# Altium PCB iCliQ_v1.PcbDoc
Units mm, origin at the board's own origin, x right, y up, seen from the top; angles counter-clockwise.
Board outline 70.5 x 34 mm, 4 copper layers (L1 (Signal), L2 (GND), L3 (GND), L4 (Signal)), stack 1.57 mm thick; 50 components, 34 nets, 172 pads, 106 vias.
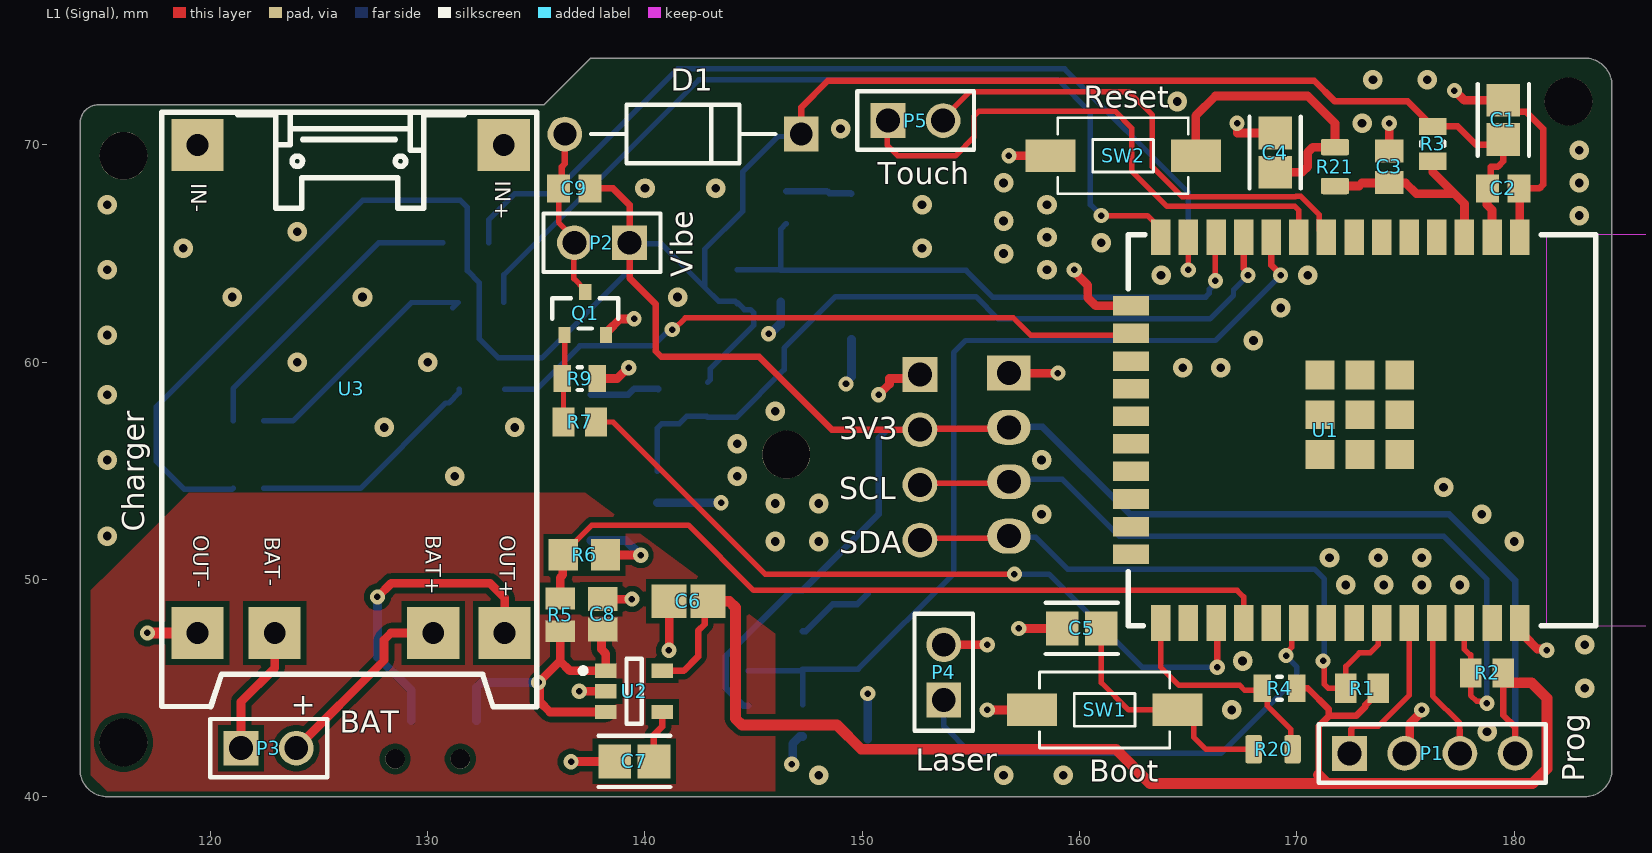
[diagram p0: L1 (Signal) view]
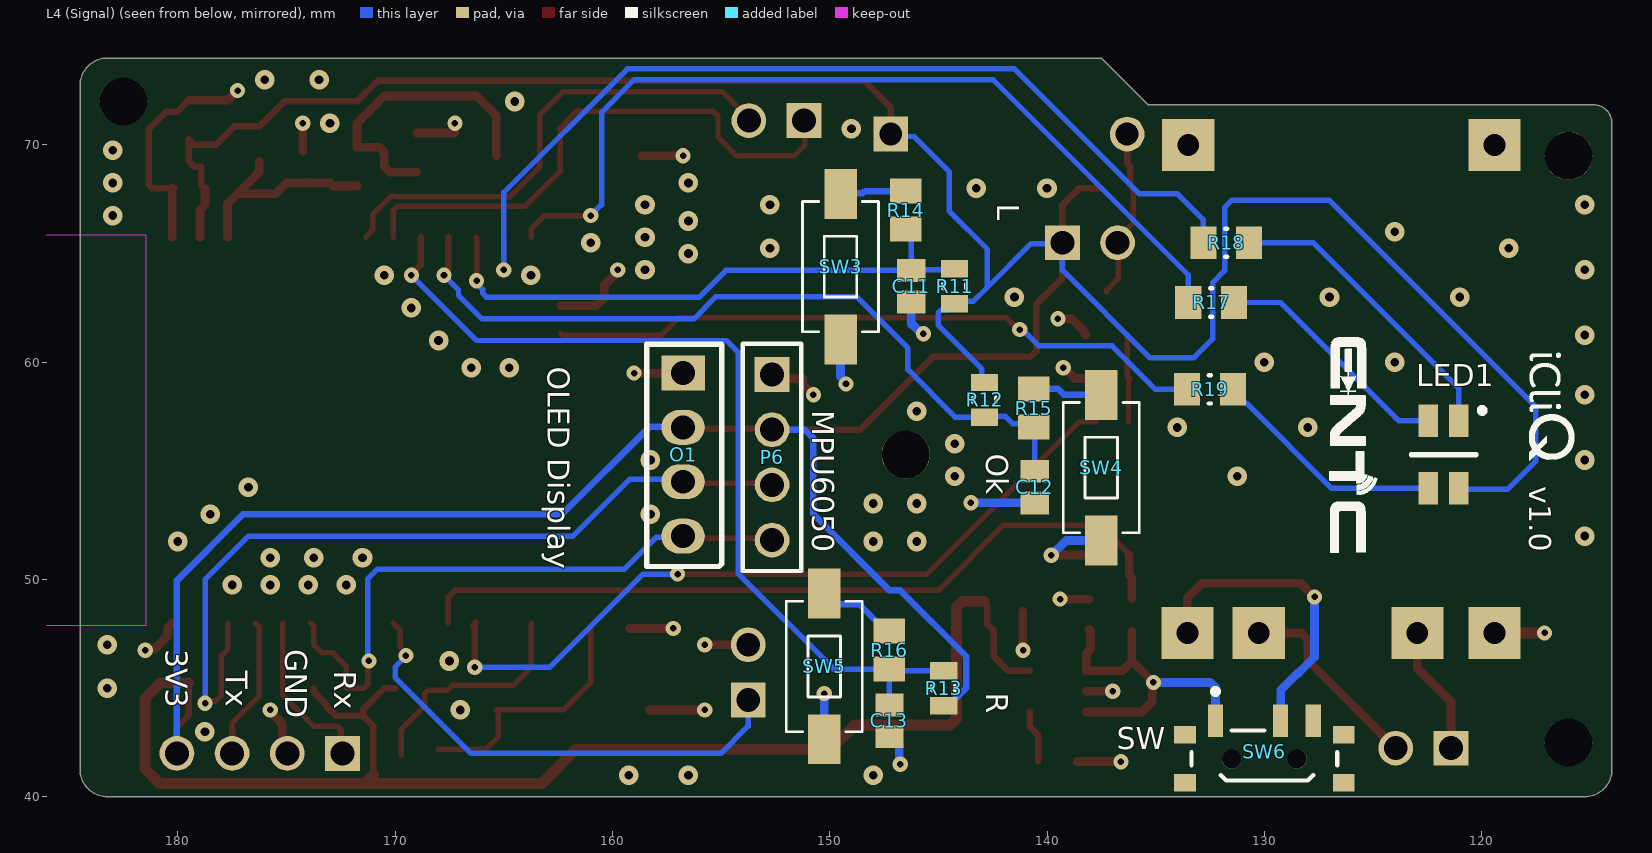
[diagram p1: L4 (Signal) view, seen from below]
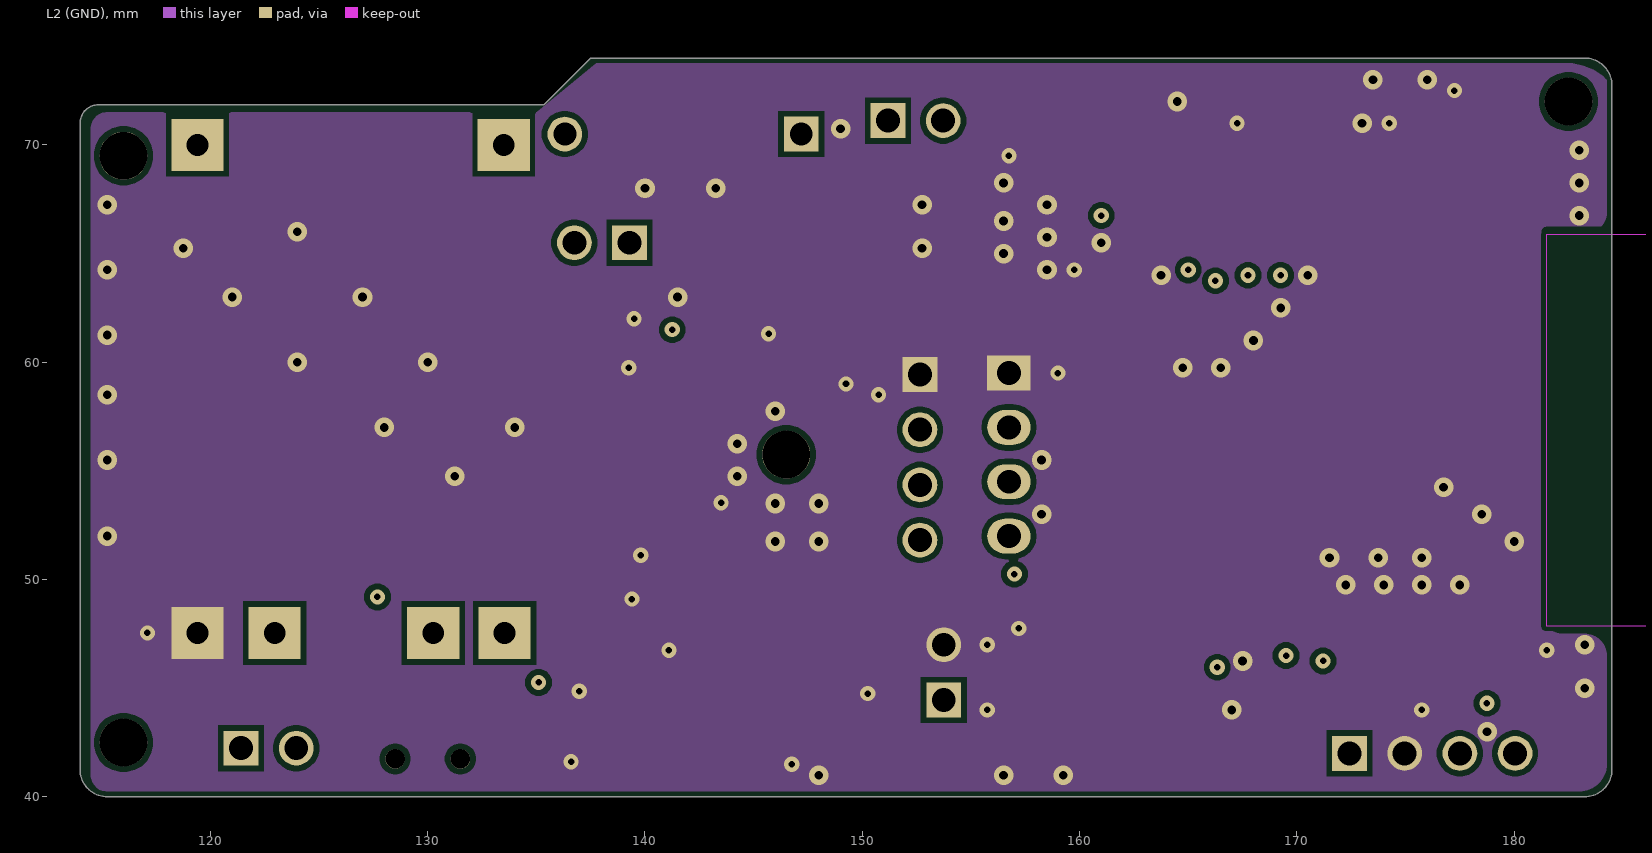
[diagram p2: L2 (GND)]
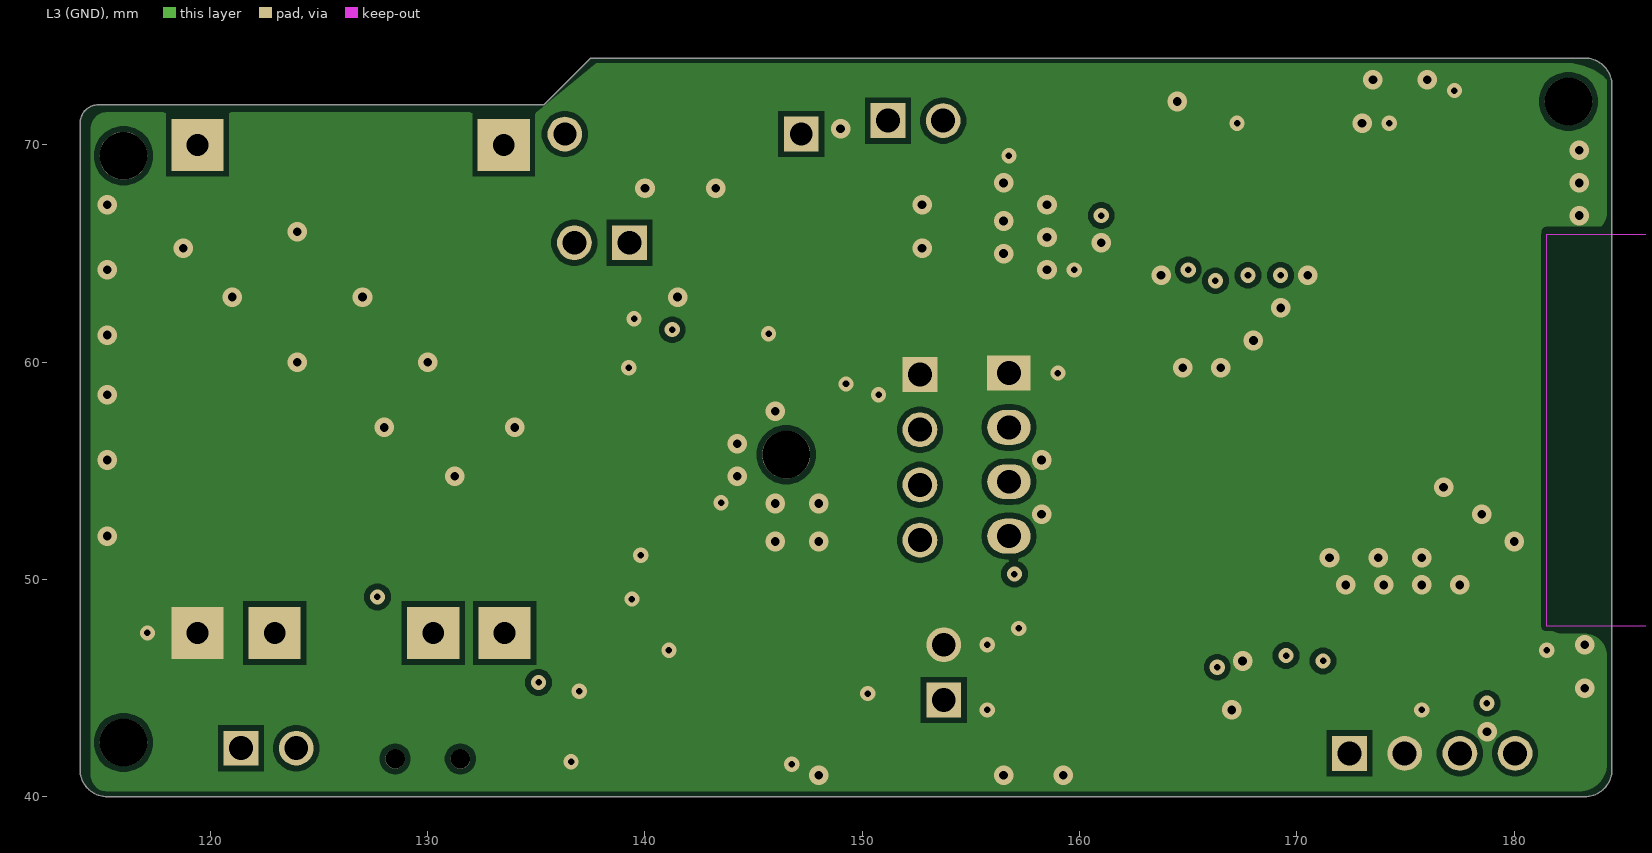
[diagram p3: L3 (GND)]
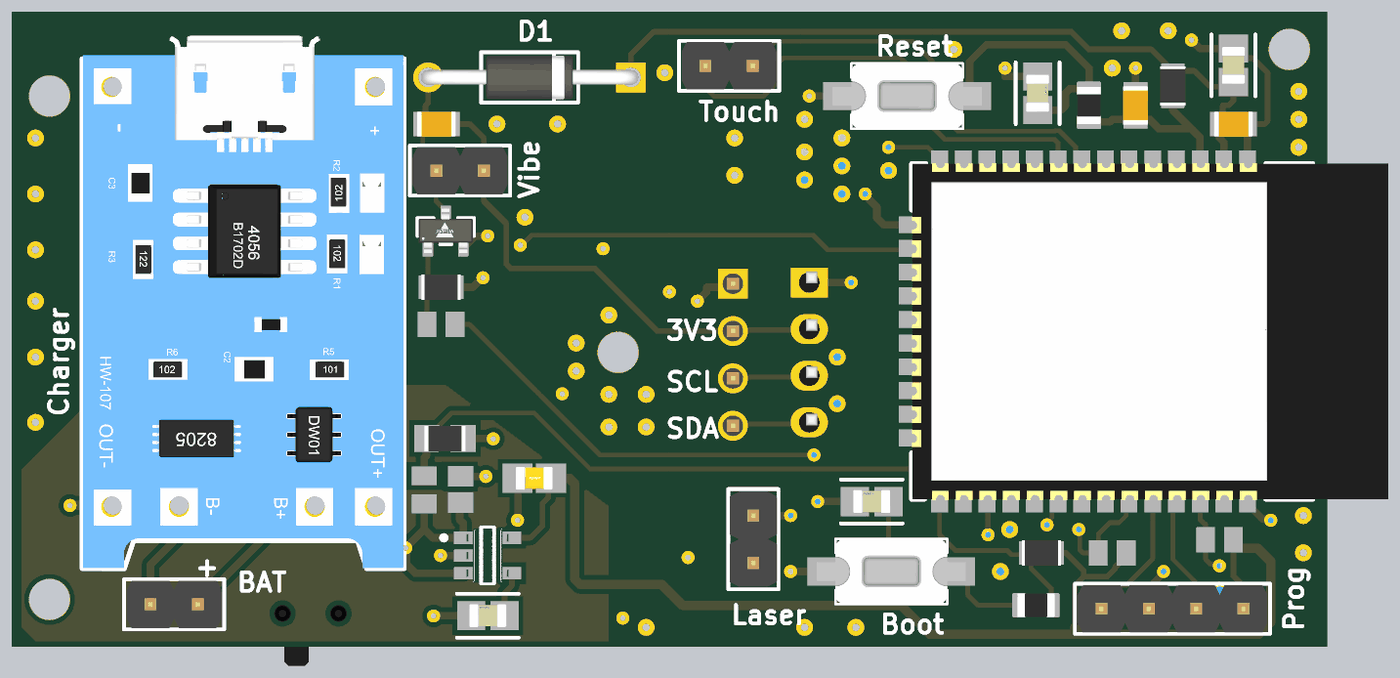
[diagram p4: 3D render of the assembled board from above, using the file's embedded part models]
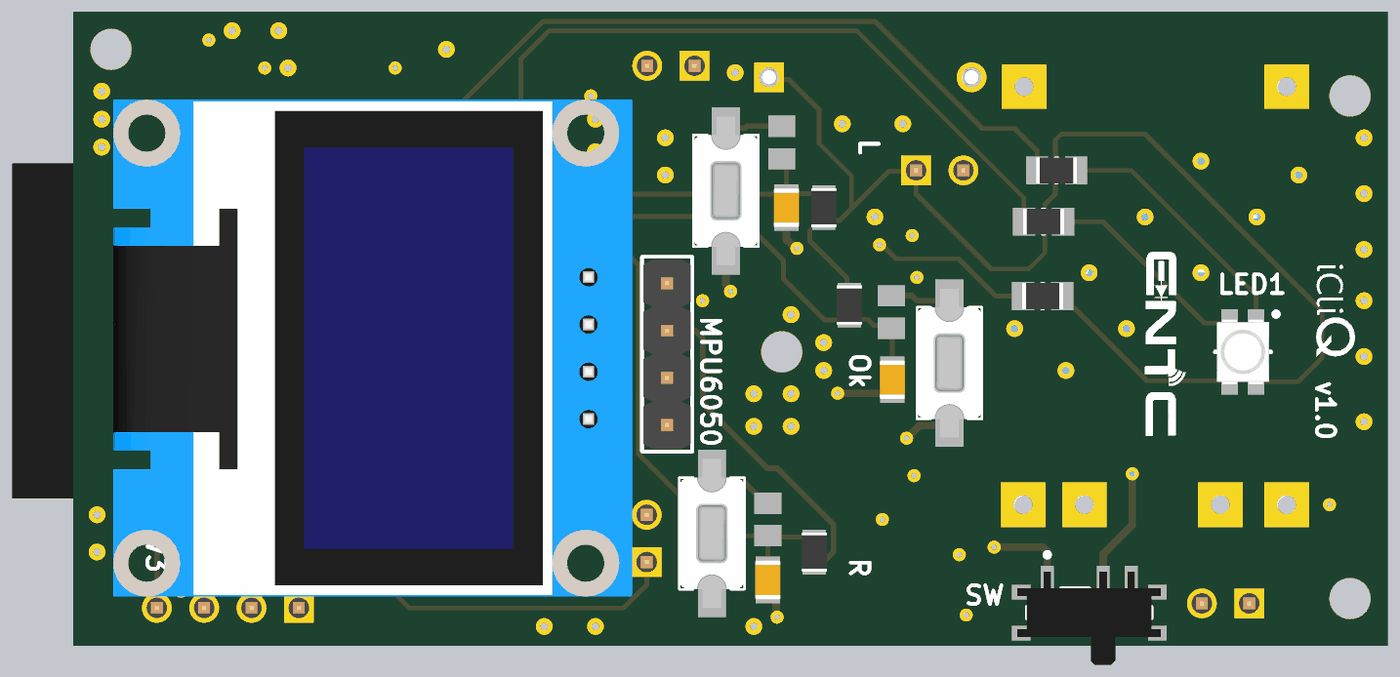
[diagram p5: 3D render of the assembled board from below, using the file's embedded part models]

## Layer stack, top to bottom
Top Solder: solder mask 0.0254, SM-001, Dk 4
L1 (Signal): signal copper 0.035
Dielectric 1: prepreg 0.2, PP-017, Dk 4.6
L2 (GND): signal copper 0.0175
Dielectric 3: core 1.065, Core-039, Dk 4.6
L3 (GND): signal copper 0.0175
Dielectric 5: prepreg 0.2, PP-017, Dk 4.6
L4 (Signal): signal copper 0.035
Bottom Solder: solder mask 0.0254, SM-001, Dk 4

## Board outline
114,41.27 114,71 cw(c114.842,71) 114.842,71.842 135.342,71.842 137.5,74 183.23,74 cw(c183.23,72.73) 184.5,72.73 184.5,41.27 cw(c183.23,41.27) 183.23,40 115.27,40 cw(c115.27,41.27)

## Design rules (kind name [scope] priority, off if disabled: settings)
Clearance [All] p1: gap=0.254 ignorepadtopadclearanceinfootprint=TRUE except(0.127: SMDPad-SMDPad; 0.2: Arc-Arc Arc-Track Arc-Text Track-Track Track-Text SMDPad-Text THPad-Text Via-Text Fill-Text Poly-Text Region-Text Text-Text Text-Hole; 0.33: Arc-THPad Track-THPad)
MinimumSolderMaskSliver [All] p1: minsoldermaskwidth=0.1
PolygonConnect [All] p1: connectstyle=Direct reliefconductorwidth=0.254 reliefentries=4 polygonreliefangle="90 Angle" airgapwidth=0.254
RoutingVias [All] p1: holewidth=0.3 width=0.7 viastyle="Through Hole" minholewidth=0.25 minwidth=0.55 maxholewidth=0.4 maxwidth=0.9
SilkToSilkClearance [All] p1: silktosilkclearance=0.15
SilkToSolderMaskClearance [IsPad] p1: minsilkscreentomaskgap=0.15 clearancetoexposedcopper=TRUE
SolderMaskExpansion [HasFootprint('No Footprint') And OnLayer('L1 (Signal)')] p1: expansion=0.038 istentingtop=FALSE
UnRoutedNet [All] p1: checkbadconnections=TRUE
Width [All] p1: maxlimit=1 minlimit=0.2 preferedwidth=0.3 midlayer1_minwidth=0.254 midlayer1_maxwidth=0.254 midlayer1_prefwidth=0.254 midlayer2_minwidth=0.254 midlayer2_maxwidth=0.254 midlayer2_prefwidth=0.254 minimp=50.000000 maximp=50.000000 favimp=50.000000
26 further rules are at their usual default settings.

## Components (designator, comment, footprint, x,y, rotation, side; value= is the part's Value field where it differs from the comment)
C1 "10uF 10V 0805" FP-C0805C-DG-IPC_A 179.5,71.151 r90 top value=10µF
C2 "Capacitor 100 nF +/-10% 50 V 0805" CAPC2013X95X50LL10T25 179.5,68 r0 top value=100nF
C3 "Capacitor 100 nF +/-10% 50 V 0805" CAPC2013X95X50LL10T25 174.25,69 r270 top value=100nF
C4 "1 nF 50V 0805" FP-C0805C-DN-IPC_A 169,69.651 r270 top value=1nF
C5 "1 nF 50V 0805" FP-C0805C-DN-IPC_A 160.099,47.75 r0 top value=1nF
C6 "2.2 uF 0805" FP-C0805C225K4RACAUTO-IPC_A 142,49 r0 top value=2.2µF
C7 "470 pF 0805" FP-C0805C-DN-IPC_A 139.51,41.631 r0 top value=470pF
C8 "1uF 10V 0805" CAPC2013X140X50LL20T25 138.049,48.398 r270 top value=1µF
C9 "Capacitor 100 nF +/-10% 50 V 0805" CAPC2013X95X50LL10T25 136.75,68 r0 top value=100nF
C11 "Capacitor 100 nF +/-10% 50 V 0805" CAPC2013X95X50LL10T25 146.25,63.5 r90 bottom value=100nF
C12 "Capacitor 100 nF +/-10% 50 V 0805" CAPC2013X95X50LL10T25 140.564,54.254 r90 bottom value=100nF
C13 "Capacitor 100 nF +/-10% 50 V 0805" CAPC2013X95X50LL10T25 147.25,43.5 r90 bottom value=100nF
D1 "1N4001-E3/54" FP-1N4001-E3-54-MFG 141.75,70.5 r180 top
LED1 "RGB LED SMD" 3528_A 121.75,55.75 r270 bottom
O1 "OLED_64" OLED_SSD1306_64 156.75,59.5 r180 bottom locked
P1 "4 pin Header" 61300411121 176.23,42 r0 top
P2 "2 pin header" 61300211121 138.02,65.5 r180 top
P3 "BAT_pins" 61300211121 122.682,42.24 r0 top
P4 "2 pin header" 61300211121 153.75,45.73 r90 top
P5 "Touch Pins" 61300211121 152.451,71.12 r0 top
P6 "MPU6050" 61300411121 152.654,55.626 r270 bottom
Q1 "SI2302 MOSFET" FP-S-03946-MFG 137.25,62.25 r90 top
R1 "2.2K 0805" RESC2013X60X40LL20T25 173,45 r0 top value=2.2k
R2 "2.2K 0805" RESC2013X60X40LL20T25 178.75,45.7 r0 top value=2.2k
R3 "10K 0805" RESC2013X60X35LL10T20 176.25,70.05 r90 top value=10k
R4 "10K 0805" RESC2013X60X35LL10T20 169.2,45 r0 top value=10k
R5 "27K 0805" RESC2013X60X40LL20T25 136.093,48.375 r270 top value=27k
R6 "Resistor 100k +/-1% 0805 125 mW" RESC2013X70X40ML20T20 137.211,51.13 r180 top value=100k
R7 "100 Ohm 0805" RESC2013X60X40LL20T25 137,57.25 r180 top value=100
R9 "10K 0805" RESC2013X60X35LL10T20 137,59.25 r180 top value=10k
R11 "10K 0805" RESC2013X60X35LL10T20 144.25,63.5 r270 bottom value=10k
R12 "10K 0805" RESC2013X60X35LL10T20 142.875,58.268 r90 bottom value=10k
R13 "10K 0805" RESC2013X60X35LL10T20 144.75,45 r270 bottom value=10k
R14 "Resistor 1K +/-5% 0805 500 mW." RESC2013X70X40NL20T20 146.5,67 r270 bottom value=1k
R15 "Resistor 1K +/-5% 0805 500 mW." RESC2013X70X40NL20T20 140.614,57.887 r270 bottom value=1k
R16 "Resistor 1K +/-5% 0805 500 mW." RESC2013X70X40NL20T20 147.25,46.75 r270 bottom value=1k
R17 "Resistor 0R +/- 1% 0805 125 mW" RESC2013X50X35ML15T15 132.45,62.75 r0 bottom value="120 Ohm"
R18 "Resistor 0R +/- 1% 0805 125 mW" RESC2013X50X35ML15T15 131.75,65.5 r0 bottom value="180 Ohm"
R19 "Resistor 0R +/- 1% 0805 125 mW" RESC2013X50X35ML15T15 132.5,58.75 r0 bottom value="120 Ohm"
R20 "Resistor 470R +/-5% 0805 125 mW" RESC0805(2012)_L 168.91,42.189 r0 top value=470
R21 "Resistor 470R +/-5% 0805 125 mW" RESC0805(2012)_L 171.75,69 r270 top value=470
SW1 "nav button" 434121050816 161.15,44 r0 top
SW2 "nav button" 434121050816 162,69.5 r0 top
SW3 "nav button" 434121050816 149.5,64.4 r90 bottom
SW4 "nav button" 434121050816 137.5,55.15 r90 bottom
SW5 "nav button" 434121050816 150.25,46 r90 bottom
SW6 "Switch_ALPS_SSSS811101_eec" ALPS_SSSS811101_0 130,41 r180 bottom
U1 "ESP32-WROOM-32D" ESP32-WROOM-32D 175.025,56.888 r270 top
U2 "3.3v LDO" FP-SOT23-5LD-PL-1-MFG 139.497,44.856 r0 top
U3 "TP4056_6PINS" TP4056_6PINs 126.388,58.062 r0 top locked

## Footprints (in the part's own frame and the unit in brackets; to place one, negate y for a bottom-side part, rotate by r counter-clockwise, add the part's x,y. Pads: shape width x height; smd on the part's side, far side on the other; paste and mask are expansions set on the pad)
3528_A [mm] "Chip LED, 4-Leads, Body 2.8x3.5mm (max), Pitch 1.42mm, IPC Medium Density"
  rect 1.5x0.9 smd: 1(1.55,0.707) 2(1.55,-0.71) 3(-1.55,0.707) 4(-1.55,-0.707)
  silkscreen extent -2.15,-1.5 0.03,1.9, body extent -1.75,-1.4 1.75,1.4, height 1.87
61300211121 [mm] "Pin Header, pitch 2.54 mm, THT, Vertical, single row, 2p"
  rect 1.6x1.6 hole 1.1: 1(-1.27,0)
  round 1.6 hole 1.1: 2(1.27,0)
  silkscreen extent -2.69,-1.35 2.69,1.35, body extent -2.54,-1.27 2.54,1.27, height 8.57
61300411121 [mm] "Pin Header, pitch 2.54 mm, THT, Vertical, single row, 4p"
  rect 1.6x1.6 hole 1.1: 1(-3.81,0)
  round 1.6 hole 1.1: 2(-1.27,0) 3(1.27,0) 4(3.81,0)
  silkscreen extent -5.23,-1.35 5.23,1.35, body extent -5.08,-1.27 5.08,1.27, height 8.57
434121050816 [mm] "6.0*3.5mm vertical type, SMD, height 5.0mm, black actuator, 160gf, T&R"
  rect 2.3x1.5 smd: 1(-3.35,0) 2(3.35,0)
  silkscreen extent -3,-1.75 3,1.75, body extent -4,-1.75 4,1.75, height 5
ALPS_SSSS811101_0 [mm]
  rect 0.7x1.5 smd paste+0 mask+0: 1(-2.25,2.5) 2(0.75,2.5) 3(2.25,2.5)
  rect 1x0.8 smd paste+0 mask+0: 4(-3.65,-0.35) 4(-3.65,1.85) 4(3.65,-0.35) 4(3.65,1.85)
  round 0.9 hole 0.9 unplated paste-1000 mask+0: ""(-1.5,0.75) ""(1.5,0.75)
  silkscreen extent -3.35,-0.25 3.35,3.97, body extent -3.85,-2.05 3.85,2.95, height 1.41
CAPC2013X95X50LL10T25 [mm] "Chip Capacitor, 2-Leads, Body 2.10x1.35mm, IPC High Density"
  rect 1.05x1.3 smd: 1(-0.725,0) 2(0.725,0)
  body extent -1.05,-0.67 1.05,0.67, height 0.95
CAPC2013X140X50LL20T25 [mm] "Chip Capacitor, 2-Leads, Body 2.00x1.25mm, IPC High Density"
  rect 1.1x1.35 smd: 1(-0.7,0) 2(0.7,0)
  body extent -1.1,-0.72 1.1,0.72, height 1.4
ESP32-WROOM-32D [mm] "Chip SMD 39 Pads 18x25.5mm w/ Antenna."
  rect 1.65x0.9 smd: 1(-8.862,5.224) 2(-8.862,3.954) 3(-8.862,2.684) 4(-8.862,1.414) 5(-8.862,0.144) 6(-8.862,-1.126) 7(-8.862,-2.396) 8(-8.862,-3.666) 9(-8.862,-4.936) 10(-8.862,-6.206) 11(-8.862,-7.476) 12(-8.862,-8.746) 13(-8.862,-10.016) 14(-8.862,-11.286) 25(8.888,-11.286) 26(8.888,-10.016) 27(8.888,-8.746) 28(8.888,-7.476) 29(8.888,-6.206) 30(8.888,-4.936) 31(8.888,-3.666) 32(8.888,-2.396) 33(8.888,-1.126) 34(8.888,0.144) 35(8.888,1.414) 36(8.888,2.684) 37(8.888,3.954) 38(8.888,5.224)
  rect 0.9x1.65 smd: 15(-5.707,-12.661) 16(-4.437,-12.661) 17(-3.167,-12.661) 18(-1.897,-12.661) 19(-0.627,-12.661) 20(0.643,-12.661) 21(1.913,-12.661) 22(3.183,-12.661) 23(4.453,-12.661) 24(5.723,-12.661)
  rect 1.33x1.33 smd: 39(-2.531,-0.292) 39(-2.531,-2.127) 39(-2.531,-3.962) 39(-0.696,-3.962) 39(-0.696,-0.292) 39(-0.696,-2.127) 39(1.139,-0.292) 39(1.139,-2.127) 39(1.139,-3.962)
  Keep-Out Layer region: -8.987,6.45 9.013,6.45 9.013,12.75 -8.987,12.75
  silkscreen extent -8.99,-12.79 9.01,8.72, body extent -9.02,-12.77 9.05,12.77, height 3
FP-1N4001-E3-54-MFG [mm]
  rect 1.6x1.6 hole 1.05 paste-1000 mask+0: 1(-5.438,0)
  round 1.6 hole 1.05 paste-1000 mask+0: 2(5.438,0)
  silkscreen extent -4.24,-1.35 4.24,1.35, body extent -5.83,-1.17 5.83,1.17, height 2.35
FP-C0805C225K4RACAUTO-IPC_A [mm]
  rect 1.603x1.556 smd paste+0 mask+0: 1(-0.9,0) 2(0.9,0)
  body extent -2.2,-1.28 2.2,1.28, height 0.25
FP-C0805C-DG-IPC_A [mm]
  rect 1.505x1.556 smd paste+0 mask+0: 1(-0.901,0) 2(0.901,0)
  silkscreen extent -1.65,-1.18 1.65,1.18, body extent -2.15,-1.28 2.15,1.28, height 0.25
FP-C0805C-DN-IPC_A [mm]
  rect 1.505x1.556 smd paste+0 mask+0: 1(-0.901,0) 2(0.901,0)
  silkscreen extent -1.65,-1.18 1.65,1.18, body extent -2.15,-1.28 2.15,1.28, height 0.25
FP-S-03946-MFG [mil]
  rect 29x22 smd paste+0 mask+0: 1(-39,37.5) 2(-39,-37.5) 3(39,0)
  silkscreen extent -28,-60 28,60, body extent -57,-64 57,64, height 10
FP-SOT23-5LD-PL-1-MFG [mm]
  rect 1x0.66 smd paste+0 mask+0: 1(-1.3,0.95) 2(-1.3,0) 3(-1.3,-0.95) 4(1.3,-0.95) 5(1.3,0.95)
  silkscreen extent -2.47,-1.5 0.35,1.5, body extent -1.4,-1.45 1.4,1.45, height 1.45
OLED_SSD1306_64 [mm]
  rect 2x1.6 hole 1.1: 1(0,0)
  oval 2x1.6 hole 1.1: 2(0,-2.5) 3(0,-5) 4(0,-7.5)
  silkscreen extent -1.68,-8.9 1.78,1.33, body extent -25.63,-16.9 2.23,9.8, height 8.47
RESC0805(2012)_L [mm] "Chip Resistor, Body 2.0x1.3mm, IPC High Density"
  rrect25% 0.76x1.3 smd: 1(-0.9,0) 2(0.89,0)
  body extent -1,-0.62 1,0.63, height 0.6
RESC2013X50X35ML15T15 [mm] "Chip Resistor, 2-Leads, Body 2.2x1.4mm, IPC Low Density"
  rect 1.2x1.5 smd: 1(-1.05,0) 2(1.05,0)
  silkscreen extent -0.05,-0.65 0.05,0.65, body extent -1.1,-0.7 1.1,0.7, height 0.5
RESC2013X60X35LL10T20 [mm] "Chip Resistor, 2-Leads, Body 2.1x1.35mm, IPC High Density"
  rect 0.8x1.25 smd: 1(-0.8,0) 2(0.8,0)
  silkscreen extent -0.1,-0.53 0.1,0.53, body extent -1.05,-0.67 1.05,0.68, height 0.6
RESC2013X60X40LL20T25 [mm] "Chip Resistor, 2-Leads, Body 2.00x1.25mm, IPC High Density"
  rect 1x1.35 smd: 1(-0.75,0) 2(0.75,0)
  body extent -1.1,-0.72 1.1,0.72, height 0.6
RESC2013X70X40ML20T20 [mm] "Chip Resistor, 2-Leads, Body 2.2x1.35mm, IPC Low Density"
  rect 1.35x1.45 smd: 1(-0.975,0) 2(0.975,0)
  body extent -1.1,-0.67 1.1,0.67, height 0.7
RESC2013X70X40NL20T20 [mm] "Chip Resistor, 2-Leads, Body 2.00x1.25mm, IPC Medium Density"
  rect 1.15x1.45 smd: 1(-0.875,0) 2(0.875,0)
  body extent -1.1,-0.72 1.1,0.72, height 0.7
TP4056_6PINs [mm] "MODULE BATTERY CHARGER 6 PINS"
  rect 2.4x2.4 hole 1: 1(-6.985,-10.52) 2(-3.431,-10.52) 3(3.87,-10.52) 4(7.151,-10.52) 5(7.112,11.938) 6(-6.985,11.938)
  silkscreen extent -8.64,-13.92 8.64,13.44, body extent -8.6,-13.88 8.6,14.67, height 4.22

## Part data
C1: library part CMP-001-00085-1, "Ceramic Capacitor, Multilayer, Ceramic, 10V, 10% +Tol, 10% -Tol, X5R, 15% TC, 10uF, Surface Mount, 0805", Capacitor Type=Ceramic, Case/Package=0805, Max Operating Temperature=85°C, Min Operating Temperature=-55°C
C2 C3 C9 C11 C12 C13: library part CMP-001-00018-6, "Chip Capacitor, 100 nF, +/- 10%, 50 V, 0805 (2012 Metric)", Capacitor Type=Ceramic, Case/Package=0805, Max Operating Temperature=125°C, Min Operating Temperature=-55°C, Tolerance=10%, Voltage Rating=50V
C4 C5: library part CMP-001-00087-1, "Ceramic Capacitor, Multilayer, Ceramic, 50V, 5% +Tol, 5% -Tol, C0G, 30ppm/Cel TC, 0.001uF, Surface Mount, 0805", Capacitor Type=Ceramic, Case/Package=0805, Max Operating Temperature=125°C, Min Operating Temperature=-55°C
C6: library part CMP-001-00091-1, "Ceramic Capacitor, Multilayer, Ceramic, 16V, 10% +Tol, 10% -Tol, X7R, 15% TC, 2.2uF, Surface Mount, 0805", Capacitor Type=Ceramic, Case/Package=0805, Max Operating Temperature=125°C, Min Operating Temperature=-55°C
C7: library part CMP-001-00088-1, "Ceramic Capacitor, Multilayer, Ceramic, 50V, 10% +Tol, 10% -Tol, X7R, 15% TC, 0.00047uF, Surface Mount, 0805", Capacitor Type=Ceramic, Case/Package=0805, Max Operating Temperature=125°C, Min Operating Temperature=-55°C
C8: library part CMP-001-00086-1, "Ceramic Capacitor, Multilayer, Ceramic, 10V, 5% +Tol, 5% -Tol, X8L, 15% TC, 1uF, Surface Mount, 0805", Capacitor Type=Ceramic, Case/Package=0805, Max Operating Temperature=150°C, Min Operating Temperature=-55°C
D1: library part CMP-004-00031-1, "Rectifier Diode, 1 Phase, 1 Element, 1A, 50V V(RRM), Silicon, DO-204AL", Forward Voltage=1.1V, Max Operating Temperature=150°C, Min Operating Temperature=-50°C
LED1: library part CMP-00030-00002-1, "Triple Color LED, Red/green/blue, Water Clear"
O1: "JST (JAPAN SOLDERLESS TERMINALS) - B8B-XH-A (LF)(SN) - HEADER, VERTICAL, 8WAY", Manufacturer=JST, Manufacturer Part Number=B8B-XH-A(LF)(SN), Supplier Part Number 1=455-2251-ND
P1 P6: library part CMP-002-00078-1, "Board Connector, 4 Contact(s), 1 Row(s), Male, Straight, 0.1 inch Pitch, Solder Terminal, Locking, Black Insulator, Plug", Max Operating Temperature=125°C, Min Operating Temperature=-40°C
P2 P3 P4 P5: library part CMP-002-00075-1, "Board Connector, 2 Contact(s), 1 Row(s), Male, Straight, 0.1 inch Pitch, Solder Terminal, Locking, Black Insulator, Plug", Max Operating Temperature=125°C, Min Operating Temperature=-40°C
Q1: library part CMP-011-00017-1, "Small Signal Field-Effect Transistor, 2.6A I(D), 20V, 1-Element, N-Channel, Silicon, Metal-oxide Semiconductor FET, TO-236AB", Max Operating Temperature=150°C
R1 R2: library part CMP-009-00187-1, "Fixed Resistor, Thin Film, 0.125W, 2200ohm, 100V, 0.5% +/-Tol, 25ppm/Cel, Surface Mount, 0805", Case/Package=0805, Max Operating Temperature=155°C, Min Operating Temperature=-55°C, Power=125mW, Tolerance=0.5%
R3 R4 R11 R12 R13: library part CMP-009-00180-1, "Fixed Resistor, Metal Glaze/thick Film, 0.125W, 10000ohm, 150V, 1% +/-Tol, 100ppm/Cel, Surface Mount, 0805", Case/Package=0805, Max Operating Temperature=155°C, Min Operating Temperature=-55°C, Power=125mW, Tolerance=1%
R5: library part CMP-009-00191-1, "Fixed Resistor, Thin Film, 0.125W, 27000ohm, 100V, 0.1% +/-Tol, 25ppm/Cel, Surface Mount, 0805", Case/Package=0805, Max Operating Temperature=155°C, Min Operating Temperature=-55°C, Power=125mW, Tolerance=0.1%
R6: library part CMP-009-00024-5, "Chip Resistor, 100 KOhm, +/- 1%, 0.125 W, -55 to 155 degC, 0805 (2012 Metric)", Case/Package=0805, Max Operating Temperature=155°C, Min Operating Temperature=-55°C, Power=125mW, Tolerance=1%, Voltage Rating=150V
R7: library part CMP-009-00189-1, "Fixed Resistor, Thin Film, 0.125W, 100ohm, 100V, 0.1% +/-Tol, 25ppm/Cel, Surface Mount, 0805", Case/Package=0805, Max Operating Temperature=155°C, Min Operating Temperature=-55°C, Power=125mW, Tolerance=0.1%
R9: library part CMP-009-00181-1, "Fixed Resistor, Metal Glaze/thick Film, 0.125W, 10000ohm, 150V, 1% +/-Tol, 100ppm/Cel, Surface Mount, 0805", Case/Package=0805, Max Operating Temperature=155°C, Min Operating Temperature=-55°C, Power=125mW, Tolerance=1%
R14 R15 R16: library part CMP-009-00178-1, "Fixed Resistor, Metal Glaze/thick Film, 0.5W, 1000ohm, 400V, 5% +/-Tol, 200ppm/Cel, Surface Mount, 0805", Case/Package=0805, Max Operating Temperature=155°C, Min Operating Temperature=-55°C, Power=500mW, Tolerance=5%
R17 R18 R19: library part CMP-009-00001-5, "Chip Resistor, 0 Ohm, +/- 1%, 125 mW, -55 to 155 degC, 0805 (2012 Metric)", Case/Package=0805, Max Operating Temperature=155°C, Min Operating Temperature=-55°C, Power=125mW, Tolerance=1%, Voltage Rating=150V
R20 R21: library part CMP-009-00122-3, "Chip Resistor, 470 Ohms, +/-5%, 125 mW, -55 to 155 degC, 0805", Case/Package=0805, Max Operating Temperature=155°C, Min Operating Temperature=-55°C, Power=125mW, Tolerance=5%
SW1 SW2 SW3 SW4 SW5: library part CMP-011-00016-1, "Keypad Switch, 1 Switches, SPST, Momentary-tactile, 0.05A, 12VDC, 2.06N, Solder Terminal, Surface Mount-straight", Max Operating Temperature=85°C, Min Operating Temperature=-40°C
SW6: Contact resistance=70mΩ, Manufacturer=ALPS, Mouser Part Number=688-SSSS811101, Package=SMD_SW_SPDT, Part Number=ON/OFF, Rating (max.)/(min.) (Resistive load)="0.3A 5V DC/50µA 3V DC", Temperature="-40°C to +85°C", Temperature Range High=+85°C, Temperature Range Low=-40°C
U1: library part CMP-016-000004-1, "Chip SMD 39 Pads Wifi 2.4GHz BLE 4.2 18x25.5mm w/ Antenna.", JLCPCB PN=C82899
U2: library part CMP-021-000001-1, "IC REG LDO 3.3V 0.5A SOT23-5"
U3: library part CMP-00029-00003-2, "MODULE BATTERY CHARGER 6 PINS"

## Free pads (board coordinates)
  round 2.2 hole 2.2: MH(116,42.5) MH(116,69.5) MH(146.5,55.75) MH(182.5,72)

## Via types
v1: diameter 0.9, hole 0.4, L1 (Signal) to L4 (Signal), 68 vias
v2: diameter 0.7, hole 0.3, L1 (Signal) to L4 (Signal), 38 vias

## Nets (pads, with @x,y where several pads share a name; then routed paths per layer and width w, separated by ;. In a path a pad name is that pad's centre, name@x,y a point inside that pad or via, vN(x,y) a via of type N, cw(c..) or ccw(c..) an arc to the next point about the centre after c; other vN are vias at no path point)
3V3: C1.1 C2.1 C6.2 C9.2 D1.1 LED1.1 O1.2 P1.4 P2.1 P6.2 R1.2 R2.2 R3.2 R4.2 R11.2 R12.2 R13.2 U1.2 U2.5 | length 250
  L1 (Signal) w0.3: C9.2 138.527,68 139.29,67.237 P2.1 139.29,63.876 140.504,62.662 140.504,61.688 140.496,61.68 140.496,60.504 140.75,60.25 145.25,60.25 148.604,56.896 P6.2 152.706,56.948 156.698,56.948 O1.2 ; U2.5 141.793,45.806 142.443,46.457 142.443,47.641 142.75,47.948 142.75,48.85 C6.2 ; D1.1 147.188,71.725 148.412,72.949 170.801,72.949 171.75,72 175.1,72 R3.2 177.4,70.85 178.25,70 179.25,70 C1.1 179.5,69.25 179.25,69 178.926,69 178.926,68.151 C2.1 C2.1@178.75,67.975 ; R4.2 170.5,45 171.475,44.025 171.475,43.725 ; 171,41 171,43.25 171.475,43.725 ; R1.2 173.75,44.825 173.154,44.229 173.154,44.158 172.721,43.725 171.475,43.725 ; R2.2@179.5,45.25 179.5,43.75 180.04,43.21 P1.4
  L1 (Signal) w0.4: C2.1@178.75,67.975 178.75,67.25 178.98,67.02 U1.2
  L1 (Signal) w0.5: C6.2 143.878,49 144.17,48.707 144.17,43.597 144.463,43.304 148.837,43.304 149.952,42.189 161.671,42.189 163.24,40.62 171.38,40.62 ; 171,41 171.04,40.96 171.38,40.62 ; R2.2@179.5,45.25 180.797,45.25 181.508,44.538 181.508,41.293 180.836,40.62 171.38,40.62
  L4 (Signal) w0.25: LED1.1 120.993,54.15 118.8,54.15 117.5,55.45 117.5,57.95 127,67.45 131.5,67.45 131.821,67.129 131.821,64.215 132.379,63.657 132.379,61.071 133.25,60.2 135.25,60.2 139.29,64.24 P2.1 139.34,65.45 140.75,65.45 142.75,63.45 ; R12.2 142.996,59.189 142.996,59.696 145,61.7 145,62.279 144.854,62.425 144.575,62.425 R11.2@144.25,62.75 ; R11.2 144.146,62.804 143.396,62.804 142.75,63.45 ; D1.1 147.076,70.388 146.114,70.388 144.5,68.774 144.5,66.95 142.75,65.2 142.75,63.45
  L4 (Signal) w0.3: R13.2 144.525,44.2 143.721,45.004 143.721,46.471 146.75,49.5 147.25,49.5 150.75,53 150.75,56.5 151.146,56.896 P6.2 ; O1.2@156.36,57 O1.2 156.773,57.023 158.293,57.023 162.316,53 177,53 180.04,49.96 P1.4
3V7: C8.2 R5.2 SW6.1 U2.1 U2.3 | length 15.7
  L1 (Signal) w0.4: R5.2 136.093,46.253 ; C8.2 137.998,47.647 137.998,46.787 138.197,46.588 U2.1 136.54,45.806 136.093,46.253 ; U2.3 135.626,43.906 135.16,44.372 135.16,45.205 v2(135.103,45.263) 136.093,46.253
  L4 (Signal) w0.4: SW6.1 132.25,45.028 132.484,45.263 v2(135.103,45.263)
3V7_in: SW6.2 U3.4 | length 14.4
  L1 (Signal) w0.4: v2@127.635,49.2 v2(127.686,49.2) 128.321,49.835 132.867,49.835 133.539,49.163 U3.4
  L4 (Signal) w0.4: v2(127.686,49.2) 127.686,46.431 128.422,45.695 128.455,45.695 129.25,44.9 SW6.2
BAT_lvl: R5.1 R6.2 U1.28 | length 36.5
  L1 (Signal) w0.25: R6.2 136.236,51.18 137.556,52.5 142,52.5 145,49.5 167.25,49.5 167.55,49.2 U1.28
  L1 (Signal) w0.4: R5.1 136.093,50.089 136.22,50.216 136.22,51.115 R6.2
Blue: R19.2 U1.16 | length 30.5
  L1 (Signal) w0.25: v2(141.25,61.5) 141.317,61.5 141.858,62.041 156.959,62.041 157.75,61.25 162.29,61.25 U1.16
  L4 (Signal) w0.25: R19.2 135,58.75 137,60.75 140.378,60.75 141.128,61.5 v2(141.25,61.5)
BOOT: R4.1 R20.2 U1.25 | length 10.7
  L1 (Signal) w0.25: U1.25 163.74,45.962 164.573,45.129 167.371,45.129 167.6,44.9 168.5,44.9 168.641,44.759 168.641,44.186 169.725,43.102 R20.2@169.725,41.915
EN: C3.2 R3.1 R21.2 U1.3 | length 9.9
  L1 (Signal) w0.4: R21.2 172.86,68.11 173,68.25 173.975,68.25 174,68.275 174.025,68.25 175,68.25 175.5,67.75 177.25,67.75 ; R3.1 176.25,68.75 177.25,67.75 ; U1.3 177.71,67.29 177.25,67.75
GND: C1.2 C2.2 C3.1 C4.1 C5.1 C6.1 C7.1 C8.1 C11.1 C12.1 C13.1 O1.1 P1.2 P4.2 P6.1 Q1.2 R6.1 R9.1 SW1.1 SW2.1 SW3.1 SW4.1 SW5.1 U1.1 U1.15 U1.38 U2.2 U3.1 | length 62.6
  L1 (Signal) w0.3: C1.2 180.023,71.529 180.544,71.529 181.334,70.738 181.334,68.176 181.159,68 C2.2
  L1 (Signal) w0.4: v2@136.6,41.6 v2(136.6,41.615) 136.6,41.631 C7.1 ; v2(136.972,44.856) U2.2 ; R9.1 138.727,59.25 139.227,59.75 v2(139.25,59.75) ; C8.1 C8.1 139.399,49.099 v2(139.4,49.1) ; R6.1 139.8,51.13 v2(139.8,51.115) v2@139.8,51.1 ; Q1.2 138.282,61.339 138.282,61.428 138.848,61.993 139.493,61.993 v2(139.5,62) ; v2(141.1,46.75) 141.122,46.772 C6.1@141.122,48.526 ; v2(150.75,58.5) 151.25,59 151.25,59.25 152.468,59.25 P6.1 ; P4.2 v2(155.75,47) ; v2(155.75,44) SW1.1@158.3,44 ; O1.1 v2(159,59.5) ; v2(156.75,69.5) SW2.1 ; v2@157.2,47.8 v2(157.2,47.75) C5.1 ; v2(159.75,64.25) 159.75,64.169 160.373,63.546 160.373,62.972 160.75,62.595 U1.15 ; v2(167.25,71) 167.25,70.552 C4.1 ; C3.1 v2(174.25,71) ; P1.2 175.19,42.23 175.19,43.358 175.75,43.919 v2(175.75,44) ; v2(177.25,72.5) 177.698,72.052 C1.2 ; C2.2 180.25,68.025 U1.1 ; U1.38 180.458,47.792 180.458,47.417 181.068,46.807 181.443,46.807 v2(181.5,46.75)
  L1 (Signal) w0.5: v2@117.1,47.6 v2(117.1,47.542) U3.1
  L4 (Signal) w0.3: P6.1 P6.1@152.832,59.258
  L4 (Signal) w0.4: SW4.1 139.115,51.8 v2(139.8,51.115) ; C12.1 v2(143.5,53.529) v2@143.5,53.5 ; v2(145.688,61.312) 145.769,61.312 146.178,61.72 146.22,61.72 146.25,61.75 C11.1 ; v2(146.75,41.5) 146.8,41.55 146.8,42.45 147.125,42.775 C13.1 ; v2(149.25,59) 149.25,59.081 149.5,59.331 SW3.1 ; SW5.1 v2(150.25,44.75)
  other v1: 148,41 156.5,41 159.25,41 178.75,43 167,44 183.25,45 167.5,46.25 183.25,47 172.25,49.75 174,49.75 175.75,49.75 177.5,49.75 171.5,51 173.75,51 175.75,51 146,51.75 148,51.75 180,51.75 115.25,52 158.25,53 178.5,53 146,53.5 148,53.5 176.75,54.25 131.25,54.75 144.25,54.75 115.25,55.5 158.25,55.5 144.25,56.25 128,57 134,57 146,57.75 115.25,58.5 164.75,59.75 166.5,59.75 124,60 130,60 168,61 115.25,61.25 169.25,62.5 121,63 127,63 141.5,63 163.75,64 170.5,64 115.25,64.25 158.5,64.25 156.5,65 118.75,65.25 152.75,65.25 161,65.5 158.5,65.75 124,66 156.5,66.5 183,66.75 115.25,67.25 152.75,67.25 158.5,67.25 140,68 143.25,68 156.5,68.25 183,68.25 183,69.75 149,70.75 173,71 164.5,72 173.5,73 176,73
Green: R17.2 U1.14 | length 40.9
  L1 (Signal) w0.25: v2(161,66.75) 163.115,66.75 163.74,66.125 U1.14
  L4 (Signal) w0.25: R17.2 133.5,64.025 142.475,73 159,73 160.5,71.5 160.5,67.25 v2(161,66.75)
Laser: P4.1 U1.30 | length 22.4
  L1 (Signal) w0.25: v2(169.5,46.5) 169.5,46.622 169.765,46.887 169.765,47.675 U1.30
  L4 (Signal) w0.25: P4.1 153.75,43.25 155,42 166.5,42 170,45.5 170,45.975 169.5,46.475 v2(169.5,46.5)
LEFT_pin: C11.2 R11.1 R14.2 U1.12 | length 27.3
  L1 (Signal) w0.25: v2(166.25,63.75) 166.25,65.72 U1.12
  L4 (Signal) w0.25: R11.1@144.25,64.25 C11.2@146.25,64.25 ; R14.2@146.5,66.375 146.25,66.125 C11.2@146.25,64.25 ; v2(166.25,63.75) 166.25,63.628 165.975,63.353 165.975,63.177 165.798,63 156,63 154.775,64.225 C11.2 C11.2@146.25,64.25
NetC4_2: C4.2 R21.1 SW2.2 | length 13.9
  L1 (Signal) w0.4: SW2.2 165.35,71.35 166.25,72.25 170.5,72.25 171.75,71 R21.1 170.734,69.9 170.5,69.666 170.5,69 170.25,68.75 C4.2
NetC5_2: C5.2 R20.1 SW1.2 | length 11.7
  L1 (Signal) w0.25: C5.2 161,45.25 162.25,44 165.25,44 165.35,44 165.25,43.9 165.25,42.75 165.811,42.189 R20.1
NetC7_2: C7.2 U2.4 | length 2.4
  L1 (Signal) w0.3: C7.2 140.411,42.85 140.797,43.235 U2.4
NetC9_1: C9.1 D1.2 P2.2 Q1.3 | length 7.9
  L1 (Signal) w0.25: C9.1 136.025,66.437 136.75,65.712 P2.2 136.728,65.478 136.728,63.851 137.25,63.33 Q1.3
  L1 (Signal) w0.3: C9.1 136.169,68.144 136.169,68.986 136.312,69.129 D1.2
NetLED1_2: LED1.2 R19.1 | length 11
  L4 (Signal) w0.25: LED1.2 126.9,54.2 130.825,58.125 130.975,58.125 131.45,58.6 R19.1
NetLED1_3: LED1.3 R18.1 | length 13.9
  L4 (Signal) w0.25: LED1.3 121.043,58.793 127.75,65.5 129.6,65.5 R18.1
NetLED1_4: LED1.4 R17.1 | length 11.6
  L4 (Signal) w0.25: LED1.4 123.8,57.3 129.25,62.75 R17.1 R17.1@131.15,62.5
NetQ1_1: Q1.1 R7.2 R9.2 | length 4.1
  L1 (Signal) w0.25: R7.2 136.25,59.2 R9.2 136.297,59.347 Q1.1
NetR14_1: R14.1 SW3.2 | length 3.1
  L4 (Signal) w0.3: R14.1 148.375,67.875 148.476,67.774 149.476,67.774 SW3.2
NetR15_1: R15.1 SW4.2 | length 3.2
  L4 (Signal) w0.3: SW4.2 139.221,58.5 139.497,58.776 140.6,58.776 R15.1
NetR16_1: R16.1 SW5.2 | length 3.7
  L4 (Signal) w0.3: R16.1 147.4,47.625 148.641,48.866 149.766,48.866 SW5.2
OK_pin: C12.2 R12.1 R15.2 U1.11 | length 35.5
  L1 (Signal) w0.3: U1.11 167.55,64.308 167.75,64.108 v2(167.75,64)
  L4 (Signal) w0.25: C12.2 140.564,56.961 R15.2 140.778,57.175 141.58,57.175 141.91,57.506 142.837,57.506 R12.1 144.218,57.468 146.405,59.655 146.405,60.655 148.772,63.022 155.228,63.022 156.25,62 166,62 167.082,63.082 167.082,63.332 v2(167.75,64)
Red: R18.2 U1.13 | length 43.6
  L1 (Signal) w0.25: v2(165,64.25) 165.01,64.26 U1.13
  L4 (Signal) w0.25: R18.2 132.8,66.55 134,67.75 135.75,67.75 141.5,73.5 159.316,73.5 165,67.816 v2(165,64.25)
RIGHT_pin: C13.2 R13.1 R16.2 U1.10 | length 41.6
  L1 (Signal) w0.3: U1.10 168.82,64.475 169.25,64.045 v2(169.25,64)
  L4 (Signal) w0.25: R13.1 147.175,45.8 R16.2 ; C13.2 R16.2 ; v2(169.25,64) 166.25,61 154.75,61 154.199,60.449 154.199,50.262 149.812,45.875 R16.2
RX: P1.1 U1.34 | length 7.8
  L1 (Signal) w0.25: P1.1 P1.1@172.5,42.08 ; 172.5,43.104 172.646,43.25 173.75,43.25 175.17,44.67 U1.34
  L1 (Signal) w0.3: P1.1@172.5,42.08 172.5,43.104
SCL: O1.3 P6.3 R2.1 U1.36 | length 38.3
  L1 (Signal) w0.25: P6.3 152.726,54.428 156.678,54.428 O1.3 ; U1.36 177.71,46.79 178,46.5 ; 178,46.55 178,46.5 ; v2(178.746,44.304) 178.66,44.39 178.284,44.39 178,44.675 R2.1 178,46.5
  L4 (Signal) w0.25: P6.3 P6.3@152.726,54.428 ; O1.3 156.86,54.61 159.207,54.61 161.817,52 176.75,52 178.746,50.004 v2(178.746,44.304)
SDA: O1.4 P6.4 R1.1 U1.33 | length 29.6
  L1 (Signal) w0.25: P6.4 152.746,51.908 156.658,51.908 O1.4 ; v2(171.203,46.252) 171.262,46.193 171.262,45.171 171.433,45 R1.1 172.25,46 172.875,46.625 173.375,46.625 173.75,47 173.75,47.85 U1.33
  L4 (Signal) w0.25: P6.4 P6.4@152.746,51.908 ; O1.4 156.798,51.952 157.979,51.952 159.452,50.479 170.802,50.479 171.262,50.019 171.262,46.311 v2(171.203,46.252)
Touch_1: P5.2 U1.8 | length 22.9
  L1 (Signal) w0.25: P5.2 153.721,71.222 154.94,72.441 162.281,72.441 163.347,71.374 163.347,68.986 164.715,67.619 169.935,67.619 169.965,67.648 170.172,67.648 171.035,66.785 171.035,66.075 U1.8
Touch_2: P5.1 U1.9 | length 26
  L1 (Signal) w0.25: P5.1 151.155,71.095 151.155,69.977 151.638,69.494 154.28,69.494 155.141,70.356 155.141,71.328 155.365,71.552 161.62,71.552 162.408,70.764 162.408,68.783 164.022,67.169 169.907,67.169 170.09,66.986 U1.9
TX: P1.3 U1.35 | length 6.6
  L1 (Signal) w0.25: U1.35 176.25,47.81 176.25,44.649 177.5,43.399 177.5,43.074
  L1 (Signal) w0.3: P1.3 177.5,43.074
VBAT+: P3.2 U3.3 | length 9.1
  L1 (Signal) w0.4: P3.2 127.991,46.279 127.991,47.219 128.314,47.542 U3.3
VBAT-: P3.1 U3.2 | length 5.9
  L1 (Signal) w0.4: P3.1 121.412,44.374 122.957,45.919 U3.2
VIBE_1: R7.1 U1.27 | length 35.4
  L1 (Signal) w0.25: R7.1 138.533,57.25 145.533,50.25 v2(157,50.25)
  L1 (Signal) w0.3: U1.27 166.395,47.885 166.339,47.828 v2(166.339,45.966)
  L4 (Signal) w0.25: v2(157,50.25) 158.589,50.25 162.872,45.966 v2(166.339,45.966)
pads on no net: SW6. SW6.3 SW6.4 U1.4 U1.5 U1.6 U1.7 U1.17 U1.18 U1.19 U1.20 U1.21 U1.22 U1.23 U1.24 U1.26 U1.29 U1.31 U1.32 U1.37 U1.39 U3.5 U3.6

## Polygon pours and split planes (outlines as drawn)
GND on L2 (GND) "GND_L02_P005" (solid, pour order 5): 135,71.5 115.25,71.5 ccw(c115.25,70.75) 114.5,70.75 114.5,41 ccw(c115.25,41) 115.25,40.25 183,40.25 ccw(c183,41.5) 184.25,41.5 184.25,46.5 ccw(c183.25,46.5) 183.25,47.5 182.25,47.5 cw(c182.25,48.5) 181.25,48.5 181.25,66 cw(c181.5,66) 181.5,66.25 184,66.25 ccw(c183.396,66.854) 184.25,66.854 184.25,73 184.244,73.006 ccw(c182.448,71.21) 182.448,73.75 137.75,73.75
GND on L3 (GND) "GND_L03_P006" (solid, pour order 6): 135,71.5 115.25,71.5 ccw(c115.25,70.75) 114.5,70.75 114.5,41 ccw(c115.25,41) 115.25,40.25 183,40.25 ccw(c183,41.5) 184.25,41.5 184.25,46.5 ccw(c183.25,46.5) 183.25,47.5 182.25,47.5 cw(c182.25,48.5) 181.25,48.5 181.25,66 cw(c181.5,66) 181.5,66.25 184,66.25 ccw(c183.396,66.854) 184.25,66.854 184.25,73 184.244,73.006 ccw(c182.448,71.21) 182.448,73.75 137.75,73.75
3V7 on L1 (Signal) "3V7_L01_P011" (solid, pour order 11): 114.5,49.5 114.5,41 115.25,40.25 146,40.25 146,47.5 137.25,54 119,54 115.5,50.5 119,54 115.5,50.5

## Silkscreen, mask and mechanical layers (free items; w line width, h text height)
Top Overlay:
  text "Reset" at 160.2,71.7 h1
  text "Touch" at 150.7,68.2 h1
  text "Vibe" at 142.2,63.9 h1 r90
  text "3V3" at 148.95,56.45 h1
  text "SCL" at 148.95,53.7 h1
  text "Charger" at 116.967,52.2 h1 r90
  text "SDA" at 148.95,51.2 h1
  text "+" at 123.7,43.783 h1
  text "BAT" at 125.95,42.95 h1
  text "Laser" at 152.45,41.2 h1
  text "Boot" at 160.45,40.7 h1
  text "Prog" at 183.217,40.7 h1 r90
Bottom Overlay:
  drawing of 22 lines, arcs and shapes, not listed
  text "L" at 142.3,67.3 h1 r90
  text "OLED Display" at 162.967,59.8 h1 r90
  text "MPU6050" at 150.8,57.8 h1 r90
  text "Ok" at 142.8,55.8 h1 r90
  text "v1.0" at 117.8,54.3 h1 r90
  text "GND" at 175.05,46.8 h1 r90
  text "3V3" at 180.55,46.8 h1 r90
  text "Rx" at 172.8,45.8 h1 r90
  text "Tx" at 177.8,45.8 h1 r90
  text "R" at 142.8,44.8 h1 r90
  text "SW" at 136.8,42.2 h1
Mechanical 1:
  lines w0.254: 114,41.27 ccw(c115.27,41.27) 115.27,40 183.23,40 ccw(c183.23,41.27) 184.5,41.27 184.5,72.73 ccw(c183.23,72.73) 183.23,74 176.5,74 161.192,74 140.5,74 137.5,74 135.342,71.842 117.428,71.842 114.842,71.842 ccw(c114.842,71) 114,71 114,41.27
